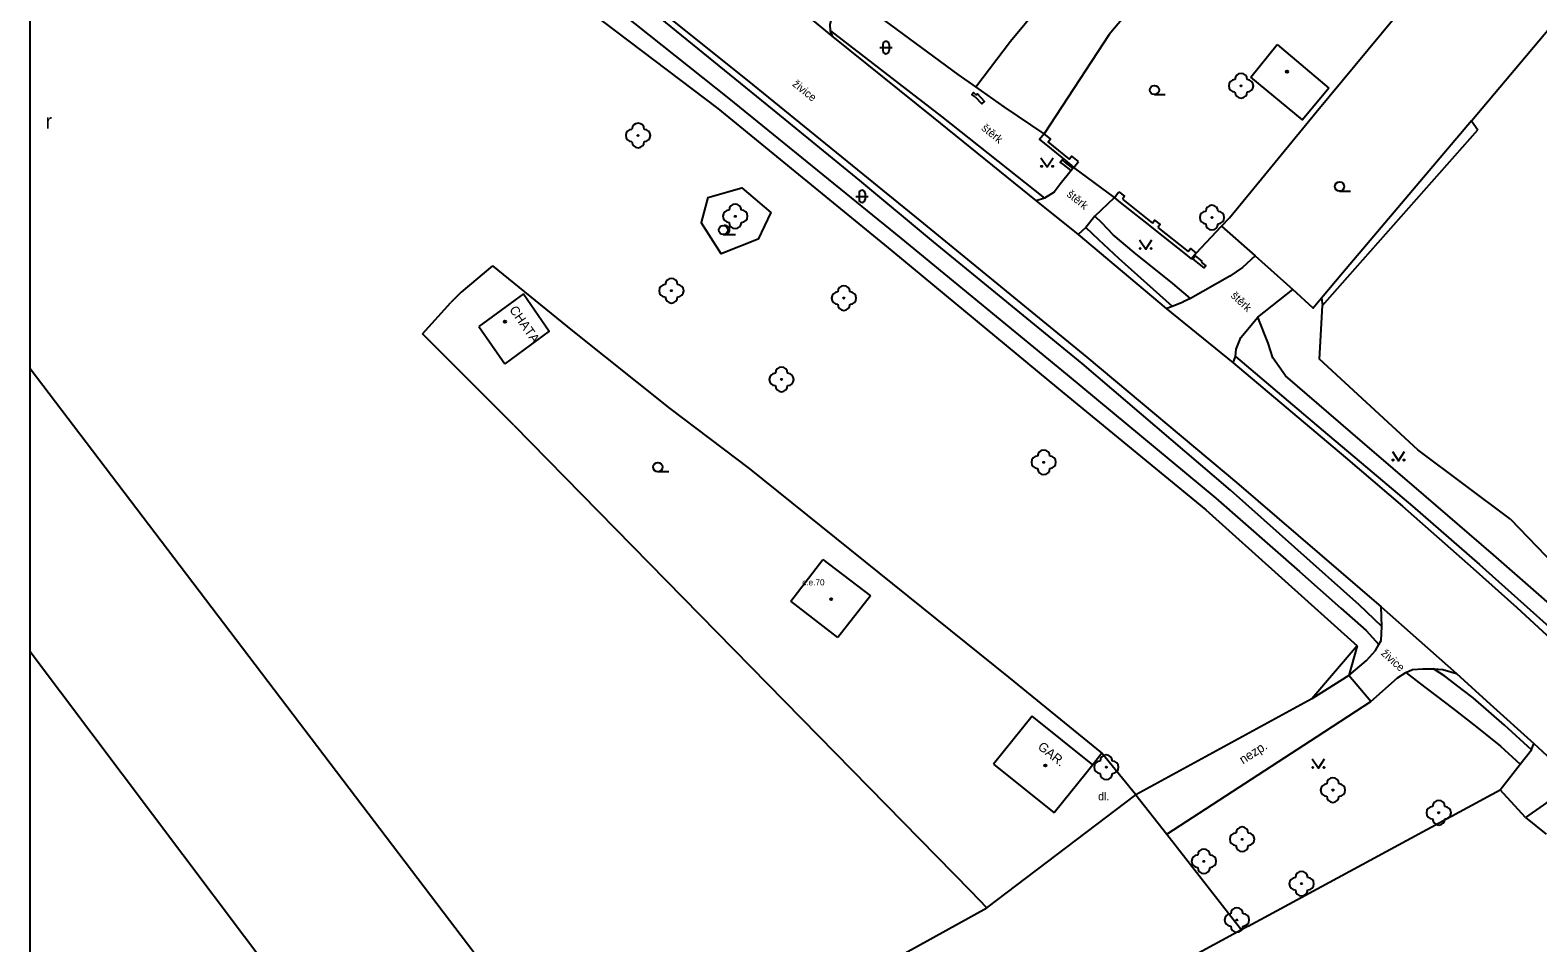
# Model space of a CAD drawing. Extents: x -594386 to -594050, y -1167541 to -1167175.
# Drawn here: x -594386.4 to -594263.8, y -1167330.4 to -1167256.2 of the extents above; entities that cross this region are included whole.
import ezdxf

# ---------------------------------------------------------------- set-up
doc = ezdxf.new("R2010")
doc.units = 0
for name, color, linetype in [('Level 14', 7, 'Continuous'), ('Level 22', 7, 'Continuous'), ('Level 24', 7, 'Continuous'), ('Level 36', 7, 'Continuous'), ('Level 39', 7, 'Continuous'), ('Level 41', 7, 'Continuous'), ('Vrstva 1', 7, 'Continuous'), ('Vrstva 10', 7, 'Continuous'), ('Vrstva 11', 7, 'Continuous'), ('Vrstva 21', 7, 'Continuous'), ('Vrstva 23', 7, 'Continuous'), ('Vrstva 40', 7, 'Continuous'), ('Vrstva 46', 7, 'Continuous'), ('Vrstva 5', 7, 'Continuous'), ('Vrstva 51', 7, 'Continuous'), ('Vrstva 52', 7, 'Continuous'), ('Vrstva 63', 7, 'Continuous'), ('Vrstva 7', 7, 'Continuous'), ('Vrstva 8', 7, 'Continuous')]:
    doc.layers.add(name, color=color, linetype=linetype)

msp = doc.modelspace()

# ---------------------------------------------------------------- linework, layer by layer
at = {"layer": 'Level 14'}
for points in [[(-594348.66, -1167246.49), (-594343.72, -1167250.47), (-594329.57, -1167261.75), (-594315.59, -1167273.12), (-594302.08, -1167284.23), (-594289.99, -1167294.24), (-594283.19, -1167300.21), (-594279.82, -1167303.19), (-594277.77, -1167305.01), (-594276.73, -1167306.15)], [(-594292.04, -1167278), (-594293.47, -1167276.79), (-594296.63, -1167274.27), (-594298.34, -1167272.83), (-594299.23, -1167271.89), (-594299.82, -1167271.31)], [(-594274.54, -1167308.41), (-594273.46, -1167309.26), (-594270.75, -1167311.31), (-594268.77, -1167312.87), (-594266.85, -1167314.41), (-594265.25, -1167315.88)]]:
    msp.add_lwpolyline(points, dxfattribs=at)
at = {"layer": 'Level 22'}
for centre in [(-594287.94, -1167260.72), (-594336.95, -1167264.76), (-594329.05, -1167271.33), (-594290.3, -1167271.43), (-594334.24, -1167277.38), (-594320.22, -1167277.98), (-594325.29, -1167284.59), (-594303.98, -1167291.33), (-594298.89, -1167316.12), (-594280.47, -1167317.98), (-594271.87, -1167319.82), (-594287.85, -1167321.98), (-594290.96, -1167323.77), (-594283.02, -1167325.59), (-594288.28, -1167328.54)]:
    msp.add_circle(centre, 0.05, dxfattribs=at)
for centre, start, end in [((-594288.44, -1167260.72), 90, 270), ((-594287.94, -1167260.22), 0, 180), ((-594287.44, -1167260.72), 270, 90), ((-594287.94, -1167261.22), 180, 0), ((-594337.45, -1167264.76), 90, 270), ((-594336.95, -1167264.26), 0, 180), ((-594336.45, -1167264.76), 270, 90), ((-594336.95, -1167265.26), 180, 0), ((-594329.05, -1167270.83), 0, 180), ((-594290.3, -1167270.93), 0, 180), ((-594329.55, -1167271.33), 90, 270), ((-594328.55, -1167271.33), 270, 90), ((-594290.8, -1167271.43), 90, 270), ((-594289.8, -1167271.43), 270, 90), ((-594329.05, -1167271.83), 180, 0), ((-594290.3, -1167271.93), 180, 0), ((-594334.24, -1167276.88), 0, 180), ((-594334.74, -1167277.38), 90, 270), ((-594334.24, -1167277.88), 180, 0), ((-594333.74, -1167277.38), 270, 90), ((-594320.72, -1167277.98), 90, 270), ((-594320.22, -1167277.48), 0, 180), ((-594319.72, -1167277.98), 270, 90), ((-594320.22, -1167278.48), 180, 0), ((-594325.29, -1167284.09), 0, 180), ((-594325.79, -1167284.59), 90, 270), ((-594325.29, -1167285.09), 180, 0), ((-594324.79, -1167284.59), 270, 90), ((-594304.48, -1167291.33), 90, 270), ((-594303.98, -1167290.83), 0, 180), ((-594303.48, -1167291.33), 270, 90), ((-594303.98, -1167291.83), 180, 0), ((-594299.39, -1167316.12), 90, 270), ((-594298.89, -1167315.62), 0, 180), ((-594298.39, -1167316.12), 270, 90), ((-594298.89, -1167316.62), 180, 0), ((-594280.47, -1167317.48), 0, 180), ((-594280.97, -1167317.98), 90, 270), ((-594279.97, -1167317.98), 270, 90), ((-594280.47, -1167318.48), 180, 0), ((-594272.37, -1167319.82), 90, 270), ((-594271.87, -1167319.32), 0, 180), ((-594271.37, -1167319.82), 270, 90), ((-594271.87, -1167320.32), 180, 0), ((-594288.35, -1167321.98), 90, 270), ((-594287.85, -1167321.48), 0, 180), ((-594287.35, -1167321.98), 270, 90), ((-594290.96, -1167323.27), 0, 180), ((-594287.85, -1167322.48), 180, 0), ((-594291.46, -1167323.77), 90, 270), ((-594290.96, -1167324.27), 180, 0), ((-594290.46, -1167323.77), 270, 90), ((-594283.52, -1167325.59), 90, 270), ((-594283.02, -1167325.09), 0, 180), ((-594282.52, -1167325.59), 270, 90), ((-594283.02, -1167326.09), 180, 0), ((-594288.78, -1167328.54), 90, 270), ((-594288.28, -1167328.04), 0, 180), ((-594287.78, -1167328.54), 270, 90), ((-594288.28, -1167329.04), 180, 0)]:
    msp.add_arc(centre, 0.5, start, end, dxfattribs=at)
at = {"layer": 'Level 24'}
for points in [[(-594309.56, -1167261.62), (-594309.82, -1167261.42), (-594309.68, -1167261.26), (-594309.45, -1167261.47)], [(-594309.56, -1167261.62), (-594309, -1167262.19), (-594308.79, -1167261.99), (-594309.35, -1167261.38), (-594309.45, -1167261.47)], [(-594302.38, -1167267.12), (-594302.63, -1167266.92), (-594302.49, -1167266.75), (-594302.24, -1167266.95)], [(-594301.75, -1167267.61), (-594302.38, -1167267.12)], [(-594302.24, -1167266.95), (-594301.62, -1167267.43)], [(-594301.62, -1167267.43), (-594301.75, -1167267.61)], [(-594291.32, -1167275.22), (-594291.86, -1167274.8), (-594291.67, -1167274.55), (-594291.13, -1167274.97), (-594291.19, -1167275.05)], [(-594291.19, -1167275.05), (-594290.8, -1167275.35), (-594290.94, -1167275.52), (-594291.32, -1167275.22)]]:
    msp.add_lwpolyline(points, dxfattribs=at)
at = {"layer": 'Level 36'}
for p, q in [((-594317.3, -1167257.61), (-594316.3, -1167257.61)), ((-594317.05, -1167257.36), (-594317.05, -1167257.86)), ((-594316.55, -1167257.36), (-594316.55, -1167257.86)), ((-594294.98, -1167261.43), (-594294.11, -1167261.43)), ((-594279.93, -1167269.29), (-594279.05, -1167269.29)), ((-594319.24, -1167269.71), (-594318.24, -1167269.71)), ((-594318.99, -1167269.46), (-594318.99, -1167269.96)), ((-594318.49, -1167269.46), (-594318.49, -1167269.96)), ((-594330.02, -1167272.82), (-594329.02, -1167272.82)), ((-594335.34, -1167292.09), (-594334.46, -1167292.09))]:
    msp.add_line(p, q, dxfattribs=at)
for points in [[(-594304.2, -1167266.57), (-594303.7, -1167267.32), (-594303.2, -1167266.57)], [(-594296.19, -1167273.25), (-594295.69, -1167274), (-594295.19, -1167273.25)], [(-594275.64, -1167290.45), (-594275.14, -1167291.2), (-594274.64, -1167290.45)], [(-594282.15, -1167315.44), (-594281.65, -1167316.19), (-594281.15, -1167315.44)]]:
    msp.add_lwpolyline(points, dxfattribs=at)
for centre, radius in [((-594294.98, -1167261.06), 0.375), ((-594304.15, -1167267.27), 0.05), ((-594303.25, -1167267.27), 0.05), ((-594279.93, -1167268.91), 0.375), ((-594330.02, -1167272.44), 0.375), ((-594296.14, -1167273.95), 0.05), ((-594295.24, -1167273.95), 0.05), ((-594335.34, -1167291.72), 0.375), ((-594275.59, -1167291.15), 0.05), ((-594274.69, -1167291.15), 0.05), ((-594282.1, -1167316.14), 0.05), ((-594281.2, -1167316.14), 0.05)]:
    msp.add_circle(centre, radius, dxfattribs=at)
for centre, radius, start, end in [((-594316.8, -1167257.36), 0.25, 0, 180), ((-594316.8, -1167257.86), 0.25, 180, 0), ((-594318.74, -1167269.46), 0.25, 0, 180), ((-594318.74, -1167269.96), 0.25, 180, 0), ((-594329.89, -1167272.44), 0.375, 260.4059, 99.5941)]:
    msp.add_arc(centre, radius, start, end, dxfattribs=at)
at = {"layer": 'Level 39'}
for centre, radius in [((-594284.2, -1167259.57), 0.09), ((-594284.2, -1167259.57), 0.0398), ((-594347.77, -1167279.89), 0.09), ((-594347.77, -1167279.89), 0.0398), ((-594321.25, -1167302.46), 0.09), ((-594321.25, -1167302.46), 0.0398), ((-594303.84, -1167315.98), 0.09), ((-594303.84, -1167315.98), 0.0398)]:
    msp.add_circle(centre, radius, dxfattribs=at)
at = {"layer": 'Vrstva 1'}
msp.add_lwpolyline([(-594266.03, -1167295.95), (-594255.36, -1167307.05)], dxfattribs=at)
at = {"layer": 'Vrstva 10'}
for points in [[(-594347.28, -1167244.92), (-594342.14, -1167248.99), (-594328.08, -1167260.27), (-594314.05, -1167271.66), (-594300.48, -1167282.78), (-594288.32, -1167292.97), (-594276.54, -1167303.08)], [(-594325.19, -1167253.37), (-594321.13, -1167256.75)], [(-594321.13, -1167256.75), (-594312.96, -1167263.29), (-594304.59, -1167270.06)], [(-594304.59, -1167270.06), (-594301.18, -1167272.8)], [(-594301.18, -1167272.8), (-594294.02, -1167278.82)], [(-594294.02, -1167278.82), (-594288.58, -1167283.24)], [(-594288.58, -1167283.24), (-594279.44, -1167290.95), (-594274.82, -1167294.9), (-594269.08, -1167299.96), (-594265.51, -1167303.14), (-594257.18, -1167310.82), (-594254.25, -1167313.59)], [(-594276.54, -1167303.08), (-594270.42, -1167308.49)], [(-594276.49, -1167304.67), (-594276.54, -1167303.08)], [(-594276.73, -1167306.15), (-594276.56, -1167305.81), (-594276.49, -1167304.67)], [(-594279.17, -1167308.66), (-594277.75, -1167307.45), (-594277.02, -1167306.63), (-594276.73, -1167306.15)], [(-594275.23, -1167308.85), (-594274.54, -1167308.41)], [(-594274.54, -1167308.41), (-594273.99, -1167308.18), (-594273.16, -1167308.11), (-594272.3, -1167308.12)], [(-594272.3, -1167308.12), (-594271.53, -1167308.18), (-594270.42, -1167308.49)], [(-594270.42, -1167308.49), (-594267.69, -1167310.99), (-594264.15, -1167314.19)], [(-594277.39, -1167310.78), (-594275.23, -1167308.85)], [(-594264.15, -1167314.19), (-594260.63, -1167317.44)]]:
    msp.add_lwpolyline(points, dxfattribs=at)
at = {"layer": 'Vrstva 11'}
for points in [[(-594269.21, -1167263.56), (-594220.22, -1167205.32), (-594228.81, -1167199.11)], [(-594276.49, -1167304.67), (-594278.35, -1167302.91), (-594288.79, -1167293.6), (-594300.84, -1167283.3), (-594312.94, -1167273.4), (-594318.93, -1167268.41), (-594326.02, -1167262.62), (-594336.86, -1167253.82), (-594346.88, -1167245.82), (-594347.58, -1167245.26)], [(-594321.32, -1167256.24), (-594321.33, -1167255.74), (-594321.18, -1167255.03), (-594316.75, -1167249.76)], [(-594321.13, -1167256.75), (-594321.32, -1167256.24)], [(-594321.32, -1167256.24), (-594312.29, -1167263.22), (-594303.92, -1167269.86)], [(-594269.21, -1167263.56), (-594268.7, -1167264.31)], [(-594301.75, -1167267.61), (-594302.64, -1167268.73), (-594303.14, -1167269.36), (-594303.92, -1167269.86)], [(-594301.62, -1167267.43), (-594301.52, -1167267.35)], [(-594303.92, -1167269.86), (-594304.59, -1167270.06)], [(-594299.82, -1167271.31), (-594298.23, -1167269.8)], [(-594299.82, -1167271.31), (-594300.55, -1167272.24)], [(-594300.55, -1167272.24), (-594301.18, -1167272.8)], [(-594300.55, -1167272.24), (-594299.53, -1167273.22), (-594297.91, -1167274.73), (-594293.55, -1167278.64)], [(-594286.8, -1167274.54), (-594287.81, -1167275.48), (-594288.84, -1167276.2), (-594292.04, -1167278)], [(-594286.57, -1167279.54), (-594283.74, -1167277.29)], [(-594294.02, -1167278.82), (-594293.55, -1167278.64)], [(-594293.55, -1167278.64), (-594292.64, -1167278.29)], [(-594292.04, -1167278), (-594292.64, -1167278.29)], [(-594281.41, -1167277.99), (-594281.31, -1167278.58)], [(-594288.39, -1167282.73), (-594288.34, -1167282.14), (-594287.95, -1167281.17), (-594286.57, -1167279.54)], [(-594250.33, -1167314.14), (-594255.34, -1167309.45), (-594259.37, -1167305.89), (-594267.41, -1167298.85), (-594273.09, -1167293.97), (-594278.06, -1167289.69), (-594284.33, -1167284.3), (-594285.35, -1167282.85), (-594285.74, -1167281.65), (-594286.57, -1167279.54)], [(-594288.58, -1167283.24), (-594288.39, -1167282.73)], [(-594288.39, -1167282.73), (-594281.26, -1167288.77), (-594277.31, -1167292.1), (-594273.99, -1167294.9), (-594268.56, -1167299.65), (-594257.99, -1167309.09), (-594251.7, -1167315.09)], [(-594278.49, -1167306.25), (-594279.17, -1167308.66)], [(-594264.34, -1167314.7), (-594266.53, -1167312.7), (-594269.07, -1167310.48), (-594269.85, -1167309.87), (-594271.38, -1167308.72), (-594272.3, -1167308.12)], [(-594279.17, -1167308.66), (-594282.18, -1167310.55)], [(-594277.39, -1167310.78), (-594279.17, -1167308.66)], [(-594282.18, -1167310.55), (-594296.48, -1167318.37)], [(-594281.74, -1167313.61), (-594277.39, -1167310.78)], [(-594293.96, -1167321.56), (-594281.74, -1167313.61)], [(-594264.34, -1167314.7), (-594264.15, -1167314.19)], [(-594265.25, -1167315.88), (-594264.34, -1167314.7)], [(-594266.87, -1167317.96), (-594265.25, -1167315.88)], [(-594262.22, -1167318.36), (-594263.37, -1167319.2), (-594264.81, -1167320.21)], [(-594293.96, -1167321.56), (-594287.9, -1167329.33)]]:
    msp.add_lwpolyline(points, dxfattribs=at)
at = {"layer": 'Vrstva 21'}
for points in [[(-594331.27, -1167269.81), (-594328.52, -1167269.01), (-594326.17, -1167271.03), (-594327.19, -1167273.18), (-594330.2, -1167274.39), (-594331.81, -1167271.83)], [(-594331.27, -1167269.81), (-594331.81, -1167271.83)]]:
    msp.add_lwpolyline(points, dxfattribs=at)
at = {"layer": 'Vrstva 23'}
for points in [[(-594344.93, -1167251.59), (-594330.46, -1167262.57), (-594316.33, -1167274.13), (-594302.78, -1167285.35)], [(-594279.28, -1167276.28), (-594268.7, -1167264.31)], [(-594281.31, -1167278.58), (-594279.28, -1167276.28)], [(-594273.58, -1167290.32), (-594281.55, -1167282.94), (-594281.31, -1167278.58)], [(-594302.78, -1167285.35), (-594290.8, -1167295.2), (-594278.49, -1167306.25)], [(-594266.03, -1167295.95), (-594273.58, -1167290.32)], [(-594278.49, -1167306.25), (-594282.18, -1167310.55)]]:
    msp.add_lwpolyline(points, dxfattribs=at)
at = {"layer": 'Vrstva 5'}
for points in [[(-594287.15, -1167260.03), (-594285.01, -1167257.37)], [(-594285.01, -1167257.37), (-594280.8, -1167260.9)], [(-594280.8, -1167260.9), (-594282.95, -1167263.5), (-594287.15, -1167260.03)], [(-594346.27, -1167277.63), (-594349.88, -1167280.28)], [(-594346.27, -1167277.63), (-594344.17, -1167280.67), (-594347.78, -1167283.32)], [(-594349.88, -1167280.28), (-594347.78, -1167283.32)], [(-594304.92, -1167311.96), (-594308.05, -1167315.86)], [(-594299.99, -1167315.92), (-594304.92, -1167311.96)], [(-594308.05, -1167315.86), (-594303.12, -1167319.82)], [(-594300.54, -1167316.6), (-594303.12, -1167319.82)], [(-594299.99, -1167315.92), (-594300.54, -1167316.6)]]:
    msp.add_lwpolyline(points, dxfattribs=at)
at = {"layer": 'Vrstva 51'}
for p, q in [((-594230.48, -1167175.43), (-594298.65, -1167256.55)), ((-594386.36, -1167283.71), (-594339.88, -1167344.83)), ((-594352.46, -1167351.78), (-594386.36, -1167306.73))]:
    msp.add_line(p, q, dxfattribs=at)
for points in [[(-594306.69, -1167257.1), (-594253.6, -1167193.11)], [(-594347.05, -1167288.31), (-594309.94, -1167326.18)], [(-594308.59, -1167327.56), (-594296.48, -1167318.37)], [(-594309.94, -1167326.18), (-594308.59, -1167327.56)], [(-594339.88, -1167344.83), (-594308.59, -1167327.56)]]:
    msp.add_lwpolyline(points, dxfattribs=at)
at = {"layer": 'Vrstva 52'}
for points in [[(-594324.54, -1167302.63), (-594321.92, -1167299.23)], [(-594321.92, -1167299.23), (-594318.07, -1167302.19)], [(-594318.07, -1167302.19), (-594320.72, -1167305.58)], [(-594320.72, -1167305.58), (-594324.54, -1167302.63)]]:
    msp.add_lwpolyline(points, dxfattribs=at)
at = {"layer": 'Vrstva 63'}
msp.add_lwpolyline([(-594386.36, -1167175.43), (-594049.75, -1167175.43), (-594049.75, -1167540.79), (-594386.36, -1167540.79)], close=True, dxfattribs=at)
at = {"layer": 'Vrstva 7'}
for points in [[(-594288.88, -1167271.46), (-594281.83, -1167262.86), (-594267.95, -1167246.12)], [(-594309.49, -1167260.8), (-594310.92, -1167259.79), (-594319.35, -1167253.56), (-594316.26, -1167250.22)], [(-594298.65, -1167256.55), (-594303.93, -1167264.62)], [(-594309.49, -1167260.8), (-594306.69, -1167257.1)], [(-594303.93, -1167264.62), (-594307.2, -1167262.42), (-594309.49, -1167260.8)], [(-594269.21, -1167263.56), (-594279.68, -1167275.94)], [(-594303.93, -1167264.62), (-594304.31, -1167265.08), (-594303.8, -1167265.5), (-594302.06, -1167266.91), (-594301.52, -1167267.35)], [(-594301.14, -1167266.88), (-594301.68, -1167266.44), (-594301.87, -1167266.68), (-594303.61, -1167265.27), (-594303.42, -1167265.04), (-594303.93, -1167264.62)], [(-594301.52, -1167267.35), (-594301.14, -1167266.88)], [(-594298.23, -1167269.8), (-594297.86, -1167269.33)], [(-594291.58, -1167274.32), (-594291.96, -1167274.79), (-594292.43, -1167274.42), (-594294.88, -1167272.47), (-594295.33, -1167272.11), (-594297.73, -1167270.2), (-594298.23, -1167269.8)], [(-594297.86, -1167269.33), (-594297.4, -1167269.69), (-594297.57, -1167269.94)], [(-594297.57, -1167269.94), (-594295.14, -1167271.88)], [(-594295.14, -1167271.88), (-594294.96, -1167271.64), (-594294.51, -1167272), (-594294.69, -1167272.24)], [(-594289.53, -1167272.14), (-594288.88, -1167271.46)], [(-594294.69, -1167272.24), (-594292.24, -1167274.18)], [(-594291.58, -1167274.32), (-594289.53, -1167272.14)], [(-594289.53, -1167272.14), (-594286.8, -1167274.54)], [(-594292.24, -1167274.18), (-594292.06, -1167273.95), (-594291.58, -1167274.32)], [(-594348.77, -1167275.36), (-594351.33, -1167277.51)], [(-594348.77, -1167275.36), (-594342.27, -1167280.64), (-594334.38, -1167286.95), (-594327.92, -1167291.84)], [(-594279.68, -1167275.94), (-594281.41, -1167277.99)], [(-594281.41, -1167277.99), (-594282.07, -1167278.81), (-594283.74, -1167277.29)], [(-594354.47, -1167280.88), (-594352.18, -1167278.34)], [(-594347.05, -1167288.31), (-594354.47, -1167280.88)], [(-594327.92, -1167291.84), (-594306.83, -1167308.81)], [(-594306.83, -1167308.81), (-594299.26, -1167314.97)], [(-594299.26, -1167314.97), (-594299.99, -1167315.92)], [(-594296.48, -1167318.37), (-594299.26, -1167314.97)], [(-594287.36, -1167329.04), (-594266.87, -1167317.96)], [(-594264.81, -1167320.21), (-594263.14, -1167321.56)], [(-594287.9, -1167329.33), (-594291.76, -1167331.42)], [(-594287.36, -1167329.04), (-594287.9, -1167329.33)]]:
    msp.add_lwpolyline(points, dxfattribs=at)
at = {"layer": 'Vrstva 8'}
for points in [[(-594298.23, -1167269.8), (-594301.52, -1167267.35)], [(-594286.8, -1167274.54), (-594283.74, -1167277.29)], [(-594351.33, -1167277.51), (-594352.18, -1167278.34)], [(-594264.81, -1167320.21), (-594266.87, -1167317.96)], [(-594296.48, -1167318.37), (-594293.96, -1167321.56)]]:
    msp.add_lwpolyline(points, dxfattribs=at)

# ---------------------------------------------------------------- texts
at = {"layer": 'Level 36'}
msp.add_text('r', height=1.2, dxfattribs=at).set_placement((-594385.11, -1167264.2))
at = {"layer": 'Level 41'}
for s, rotation, p in [('CHATA', 305, (-594347.45, -1167278.93)), ('GAR.', 321.23, (-594304.52, -1167314.57))]:
    msp.add_text(s, height=0.75, rotation=rotation, dxfattribs=at).set_placement(p)
at = {"layer": 'Vrstva 40'}
for s, height, rotation, p in [('živice', 0.65, 320.9292, (-594324.46, -1167260.67)), ('štěrk', 0.65, 321.03, (-594309.09, -1167264.26)), ('štěrk', 0.65, 321.2131, (-594302.16, -1167269.64)), ('štěrk', 0.65, 317, (-594288.82, -1167277.85)), ('živice', 0.65, 318, (-594276.61, -1167306.93)), ('nezp.', 0.75, 33.0469, (-594287.78, -1167315.9))]:
    msp.add_text(s, height=height, rotation=rotation, dxfattribs=at).set_placement(p)
msp.add_text('dl.', height=0.65, dxfattribs=at).set_placement((-594299.56, -1167318.81))
at = {"layer": 'Vrstva 46'}
msp.add_text('c.e.70', height=0.5, dxfattribs=at).set_placement((-594323.61, -1167301.34))

doc.saveas('drawing.dxf')
